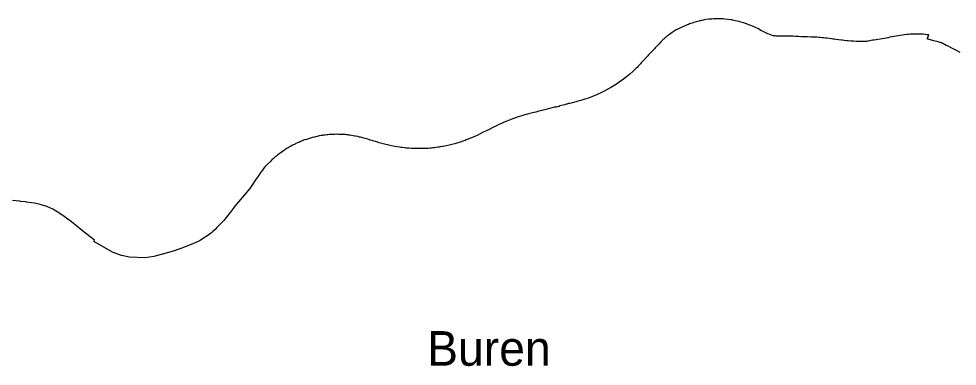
# Model space of a CAD drawing. Extents: x 113371 to 291721, y 393993 to 520143.
# Drawn here: x 148639 to 162187, y 439176 to 444191 of the extents above; entities that cross this region are included whole.
import ezdxf

# ---------------------------------------------------------------- set-up
doc = ezdxf.new("R2010")
doc.units = 0
doc.layers.add('Default', color=7, linetype='Continuous')
doc.layers.add('plaatsnamen', color=7, linetype='Continuous')

msp = doc.modelspace()

# ---------------------------------------------------------------- linework, layer by layer
at = {"layer": 'Default'}
for points in [[(158983.235625, 444163.3325), (158944.745625, 444171.1325), (158932.025625, 444173.8425), (158920.835625, 444175.3625), (158831.645625, 444185.8625), (158806.385625, 444188.7425), (158796.895625, 444189.7625), (158766.535625, 444191.4525), (158748.565625, 444191.4525), (158714.315625, 444190.9425), (158669.045625, 444189.0725), (158642.425625, 444188.0525), (158603.265625, 444183.6425), (158559.515625, 444178.5425), (158534.085625, 444173.9625), (158504.575625, 444167.8625), (158496.575625, 444166.2325), (158477.415625, 444162.8325), (158467.285625, 444160.5725), (158459.955625, 444158.9325), (158436.725625, 444153.5025), (158417.225625, 444148.2425), (158382.645625, 444137.5625), (158358.735625, 444129.9225), (158343.135625, 444124.5025), (158322.965625, 444116.5225), (158307.025625, 444110.0825), (158287.525625, 444103.1325), (158234.155625, 444081.9925), (158180.035625, 444056.4925), (158153.485625, 444042.9825), (158138.635625, 444035.7025), (158129.305625, 444029.6825), (158102.855625, 444012.8425), (158087.675625, 444003.4825), (158073.295625, 443994.1325), (158065.535625, 443988.7325), (158042.465625, 443971.8925)], [(159934.375625, 443932.7825), (159894.015625, 443934.9525), (159854.255625, 443936.9325), (159812.505625, 443938.7125), (159791.635625, 443939.7025), (159769.965625, 443940.4925), (159756.445625, 443940.8825), (159733.575625, 443941.1125), (159729.055625, 443941.1125), (159702.345625, 443941.1025), (159661.825625, 443940.9325), (159636.215625, 443940.7525), (159592.815625, 443940.4125), (159576.195625, 443941.0925), (159566.195625, 443941.4325), (159555.175625, 443943.1225), (159531.775625, 443947.5325), (159507.695625, 443954.1425), (159493.625625, 443959.2225), (159470.225625, 443968.2125), (159451.065625, 443976.1825), (159412.405625, 443993.6425), (159384.425625, 444006.6925), (159360.005625, 444018.7325), (159324.055625, 444039.2425), (159306.925625, 444048.7325), (159286.075625, 444058.5725), (159263.355625, 444069.0825), (159231.645625, 444083.1525), (159206.885625, 444092.8125), (159178.395625, 444104.3425), (159142.965625, 444117.2225), (159129.565625, 444121.6325), (159102.775625, 444130.6125), (159062.415625, 444143.1625), (159039.015625, 444150.1125), (159012.225625, 444157.0625), (158983.235625, 444163.3325)], [(158042.465625, 443971.8925), (158018.435625, 443954.0225), (158003.885625, 443943.6325), (157996.915625, 443938.2225), (157981.835625, 443925.9625), (157969.675625, 443915.5725), (157962.325625, 443909.5425), (157955.375625, 443903.7325), (157946.865625, 443896.6625), (157939.145625, 443890.2225), (157932.605625, 443883.7825), (157929.695625, 443880.8025), (157925.495625, 443876.5025), (157917.635625, 443867.9825), (157912.915625, 443862.9725), (157908.435625, 443858.2225), (157881.585625, 443829.5425), (157868.915625, 443816.2425), (157854.335625, 443800.8625), (157841.305625, 443786.7325), (157827.495625, 443772.1925), (157814.835625, 443758.6825), (157806.775625, 443750.1625), (157800.065625, 443743.1025), (157787.975625, 443730.4225), (157773.785625, 443715.2525), (157752.495625, 443692.6025), (157732.355625, 443671.2025), (157719.315625, 443657.2825), (157704.925625, 443642.1125), (157692.085625, 443628.1825), (157677.145625, 443611.5625), (157671.625625, 443605.3825), (157670.635625, 443604.2825), (157665.085625, 443598.0525), (157645.345625, 443576.6525), (157624.825625, 443554.6325), (157612.355625, 443541.5425)], [(161764.985625, 443925.5925), (161768.375625, 443935.7725), (161776.035625, 443958.6725), (161757.845625, 443960.1125), (161747.145625, 443961.0625), (161729.015625, 443963.3425), (161694.925625, 443967.3425), (161685.135625, 443968.2925), (161676.065625, 443969.0525), (161665.185625, 443970.1925), (161644.695625, 443970.3625), (161626.195625, 443970.5325), (161593.015625, 443969.3425), (161564.185625, 443968.3525), (161542.065625, 443967.9525), (161510.505625, 443967.9125), (161481.855625, 443966.5425), (161460.095625, 443965.7425), (161452.665625, 443965.1625), (161424.555625, 443960.5225), (161394.455625, 443955.1125), (161364.175625, 443949.7025), (161334.795625, 443944.3025), (161306.325625, 443939.4725), (161275.495625, 443934.8225), (161245.575625, 443929.2225), (161216.205625, 443923.6225), (161188.755625, 443918.5425), (161187.005625, 443918.2225), (161161.435625, 443913.3925), (161132.245625, 443907.6025), (161102.865625, 443902.7725), (161073.125625, 443897.9325), (161042.665625, 443892.9125), (161014.735625, 443888.2725), (160986.265625, 443883.6325), (160964.325625, 443880.7325), (160945.645625, 443876.8725)], [(160945.645625, 443876.8725), (160903.935625, 443868.7625), (160897.315625, 443867.4025), (160883.265625, 443864.5125), (160867.305625, 443863.9225), (160842.945625, 443862.8825), (160825.365625, 443862.6125), (160806.285625, 443862.2125), (160774.275625, 443862.2025), (160753.005625, 443862.9925), (160730.345625, 443863.9825), (160691.175625, 443866.9525), (160652.815625, 443869.9325), (160610.865625, 443873.4925), (160589.395625, 443875.2825), (160556.795625, 443878.0525), (160531.945625, 443880.4325), (160510.275625, 443882.6225), (160475.095625, 443887.1825), (160436.725625, 443892.7425), (160409.695625, 443896.5125), (160390.215625, 443899.2925), (160371.125625, 443902.0725), (160342.105625, 443905.2425), (160302.745625, 443909.8125), (160285.055625, 443911.7925), (160254.835625, 443914.9725), (160238.735625, 443916.5525), (160208.915625, 443919.3325), (160188.635625, 443921.3125), (160159.815625, 443924.0925), (160140.925625, 443925.2825), (160112.895625, 443926.4625), (160072.535625, 443927.2525), (160024.825625, 443929.0225), (159983.475625, 443930.8025), (159960.815625, 443931.7925), (159934.375625, 443932.7825)], [(162228.315625, 443705.6725), (162165.355625, 443739.9825), (162120.635625, 443761.8325), (162055.405625, 443793.7225), (162027.555625, 443807.0025), (162004.275625, 443819.3225), (161987.655625, 443828.3625), (161973.095625, 443836.0525), (161960.325625, 443842.6125), (161952.645625, 443846.0225), (161945.465625, 443848.8825), (161937.585625, 443851.2425), (161913.925625, 443857.6125), (161897.265625, 443861.8225), (161866.975625, 443869.7025), (161851.265625, 443873.7125), (161833.495625, 443878.1825), (161815.365625, 443882.8825), (161799.655625, 443886.9025), (161781.785625, 443891.1725), (161766.395625, 443895.3825), (161755.805625, 443898.3425), (161759.715625, 443910.1925), (161764.985625, 443925.5925)], [(157612.355625, 443541.5425), (157592.985625, 443520.9625), (157579.175625, 443506.2125), (157564.215625, 443490.2125), (157551.915625, 443477.9525), (157544.645625, 443471.0225), (157525.465625, 443452.8125), (157501.605625, 443430.1425), (157458.705625, 443390.4525), (157411.255625, 443353.1025), (157367.095625, 443317.6925), (157306.835625, 443274.8825), (157268.675625, 443248.8125), (157241.745625, 443231.6825), (157194.395625, 443202.8825), (157143.345625, 443173.6925), (157100.985625, 443151.1225), (157041.805625, 443121.2125), (156970.575625, 443088.9925), (156954.345625, 443082.3325), (156922.035625, 443069.9925), (156888.985625, 443057.4125), (156858.825625, 443046.0625), (156832.865625, 443036.7725), (156810.005625, 443028.9325), (156782.155625, 443020.1425), (156762.635625, 443014.7725), (156752.895625, 443012.0925), (156726.775625, 443004.6225), (156709.935625, 443000.0025), (156686.545625, 442993.5225), (156662.235625, 442986.9625), (156646.145625, 442983.0825), (156630.505625, 442979.0725), (156613.755625, 442974.7025), (156595.885625, 442970.5325), (156577.475625, 442966.0725), (156557.465625, 442961.0825)], [(156557.465625, 442961.0825), (156539.885625, 442956.5425), (156520.125625, 442951.5525), (156496.315625, 442945.2325), (156471.055625, 442939.2925), (156444.605625, 442932.4825), (156444.025625, 442928.8525), (156441.555625, 442926.5425), (156437.675625, 442925.0525), (156434.045625, 442923.9025), (156413.365625, 442917.9125), (156399.005625, 442914.9425), (156394.225625, 442914.3625), (156392.405625, 442914.3625), (156390.265625, 442915.6825), (156388.035625, 442918.0825), (156377.465625, 442915.4325), (156352.055625, 442909.4125), (156319.325625, 442900.8725), (156282.975625, 442891.7425), (156247.525625, 442882.2125), (156215.465625, 442874.0025), (156146.055625, 442856.0025), (156104.415625, 442845.6525), (156055.705625, 442833.5225), (156036.035625, 442828.2025), (155995.305625, 442818.0925), (155963.865625, 442808.9125), (155912.185625, 442794.5525), (155887.915625, 442786.7025), (155850.505625, 442774.6225), (155808.105625, 442761.0025), (155765.585625, 442745.5325), (155733.295625, 442733.4325), (155687.205625, 442714.8425), (155648.485625, 442698.8625), (155616.645625, 442684.9025), (155582.075625, 442669.7725)], [(155582.075625, 442669.7725), (155571.505625, 442665.1425), (155537.375625, 442648.0625), (155484.455625, 442621.8225), (155438.055625, 442598.5025), (155391.785625, 442575.4425), (155345.595625, 442552.6125), (155301.405625, 442530.4025), (155265.305625, 442512.7625), (155256.405625, 442508.3325), (155233.575625, 442496.9725), (155223.625625, 442492.8525), (155161.975625, 442468.8725), (155099.415625, 442441.7825), (155081.845625, 442435.3225), (155076.235625, 442433.2625), (155062.525625, 442428.2125), (155033.225625, 442418.4825), (155013.855625, 442412.0625), (154977.075625, 442400.8525), (154965.155625, 442396.8925), (154933.075625, 442388.0825), (154893.165625, 442377.4725), (154850.125625, 442367.0625), (154809.745625, 442358.0625), (154765.585625, 442348.8925), (154754.145625, 442346.5425), (154724.555625, 442341.6925), (154707.425625, 442338.6225), (154688.085625, 442336.0825), (154659.675625, 442332.2225), (154639.285625, 442329.4025), (154616.485625, 442326.6525), (154599.365625, 442324.9025), (154577.845625, 442323.2325), (154551.205625, 442320.9225), (154512.475625, 442318.5525), (154465.555625, 442316.4625)], [(152886.445625, 442478.4125), (152874.085625, 442475.4925), (152864.945625, 442473.3325), (152849.775625, 442469.0225), (152833.585625, 442464.1925), (152821.695625, 442460.3825), (152805.255625, 442455.5625), (152790.585625, 442450.4825), (152769.425625, 442443.5425), (152764.285625, 442441.8625), (152750.115625, 442436.7825), (152735.195625, 442430.7025), (152721.795625, 442425.1125), (152706.615625, 442419.0325), (152695.235625, 442414.2125), (152679.805625, 442407.3625), (152664.885625, 442400.5225), (152641.115625, 442389.1125), (152628.465625, 442383.5325), (152615.825625, 442377.7025), (152603.685625, 442371.6125), (152591.145625, 442365.2025), (152590.285625, 442364.7725), (152578.145625, 442358.6825), (152565.755625, 442351.8425), (152551.845625, 442344.4925), (152536.925625, 442336.1225), (152526.305625, 442329.7925), (152514.675625, 442322.4425), (152494.195625, 442308.7525), (152481.045625, 442300.3925), (152455.005625, 442282.6525), (152434.015625, 442268.2125), (152412.525625, 442252.5025), (152398.875625, 442242.6225), (152378.905625, 442227.1725), (152369.045625, 442219.3125), (152358.175625, 442210.4525)], [(153573.345625, 442480.7825), (153559.675625, 442484.3225), (153543.115625, 442488.2125), (153531.855625, 442490.6425), (153499.525625, 442496.8625), (153491.865625, 442498.3525), (153466.635625, 442503.2625), (153440.365625, 442507.7325), (153419.825625, 442511.0725), (153405.385625, 442513.2025), (153391.365625, 442515.0825), (153371.565625, 442517.1325), (153350.395625, 442518.8825), (153344.105625, 442519.4025), (153312.265625, 442521.7025), (153286.555625, 442522.2425), (153282.345625, 442522.3325), (153272.505625, 442522.5725), (153256.815625, 442523.0625), (153231.765625, 442523.5425), (153224.645625, 442523.4725), (153203.175625, 442523.2625), (153176.865625, 442522.4825), (153160.675625, 442521.9525), (153144.485625, 442520.9325), (153125.755625, 442520.1525), (153102.235625, 442518.1025), (153090.845625, 442516.5725), (153064.035625, 442513.5125), (153046.325625, 442511.2125), (153035.345625, 442509.8025), (153020.515625, 442507.9025), (153005.335625, 442505.1025), (152977.765625, 442499.7625), (152945.135625, 442493.4025), (152921.355625, 442487.5625), (152906.435625, 442483.7525), (152886.445625, 442478.4125)], [(154465.555625, 442316.4625), (154459.305625, 442316.6825), (154432.015625, 442316.5625), (154390.935625, 442316.7625), (154376.895625, 442317.1425), (154357.625625, 442317.6725), (154329.825625, 442318.6425), (154307.845625, 442320.2925), (154271.865625, 442322.2125), (154267.645625, 442322.4325), (154266.875625, 442322.4725), (154227.145625, 442325.6025), (154225.815625, 442325.7125), (154205.215625, 442327.9625), (154174.205625, 442332.3625), (154155.795625, 442335.4625), (154135.345625, 442338.3325), (154094.775625, 442344.6825), (154066.705625, 442349.3625), (154019.615625, 442358.4025), (153980.285625, 442366.6525), (153965.195625, 442369.8225), (153938.415625, 442376.5225), (153918.875625, 442381.0425), (153898.535625, 442386.5725), (153859.505625, 442397.4625), (153843.855625, 442401.9625), (153823.675625, 442407.7725), (153820.295625, 442408.7425), (153786.665625, 442418.6525), (153765.715625, 442424.8025), (153748.305625, 442430.0225), (153741.055625, 442432.1325), (153712.885625, 442440.3325), (153676.885625, 442451.2025), (153639.475625, 442462.0925), (153605.085625, 442471.6325), (153573.345625, 442480.7825)], [(152358.175625, 442210.4525), (152346.285625, 442201.3325), (152336.935625, 442193.7325), (152326.825625, 442185.1125), (152309.385625, 442169.6625), (152297.755625, 442159.0225), (152286.375625, 442148.1325), (152275.765625, 442137.7525), (152217.965625, 442082.4325), (152193.525625, 442053.9225), (152174.025625, 442028.8125), (152157.545625, 442007.0125), (152143.725625, 441987.6825), (152134.605625, 441975.3425), (152118.045625, 441952.2925), (152104.325625, 441933.4525), (152083.805625, 441905.6625), (152068.785625, 441883.7525), (152057.685625, 441867.0525), (152046.665625, 441850.5925), (152039.145625, 441839.1625), (152036.685625, 441835.4325), (152023.185625, 441814.7125), (152002.945625, 441784.1125), (151984.625625, 441756.6525), (151974.285625, 441741.8725), (151810.185625, 441551.3125), (151782.445625, 441515.8325), (151782.375625, 441515.7425), (151762.215625, 441490.0125), (151691.925625, 441395.8625), (151672.725625, 441371.4925), (151656.035625, 441350.5325), (151614.365625, 441298.7725), (151597.875625, 441278.8925), (151557.465625, 441234.3025), (151524.405625, 441201.5925), (151500.495625, 441177.3825)], [(148652.695625, 441557.4525), (148550.345625, 441567.1125)], [(151500.495625, 441177.3825), (151473.465625, 441151.1125), (151439.845625, 441121.0725), (151438.625625, 441119.9925), (151419.485625, 441103.0625), (151401.235625, 441086.8225), (151392.535625, 441080.4725), (151355.205625, 441055.6725), (151290.975625, 441014.8825), (151256.665625, 440993.1125), (151227.735625, 440978.0925), (151160.275625, 440948.6825), (151102.275625, 440921.9025), (150978.645625, 440875.3025), (150854.555625, 440831.8125), (150591.125625, 440759.5925), (150465.465625, 440739.9025), (150239.365625, 440751.2525), (150121.065625, 440773.8025), (150001.235625, 440818.3125), (149720.325625, 440977.6725), (149734.675625, 440995.3625), (149628.815625, 441076.1225), (149536.195625, 441148.7525), (149448.545625, 441220.7125), (149381.125625, 441274.1525), (149296.335625, 441337.3925), (149217.905625, 441392.2125), (149131.455625, 441441.8925), (149042.225625, 441481.1825), (148947.575625, 441511.0925), (148865.945625, 441527.8125), (148821.655625, 441535.1825), (148750.555625, 441546.0725), (148735.075625, 441547.8525), (148670.805625, 441555.2825), (148654.895625, 441557.2125), (148652.695625, 441557.4525)]]:
    msp.add_lwpolyline(points, dxfattribs=at)

# ---------------------------------------------------------------- texts
at = {"layer": 'plaatsnamen'}
msp.add_text('Buren', height=500, dxfattribs=at).set_placement((154534.032304, 439183.120338))

doc.saveas('drawing.dxf')
